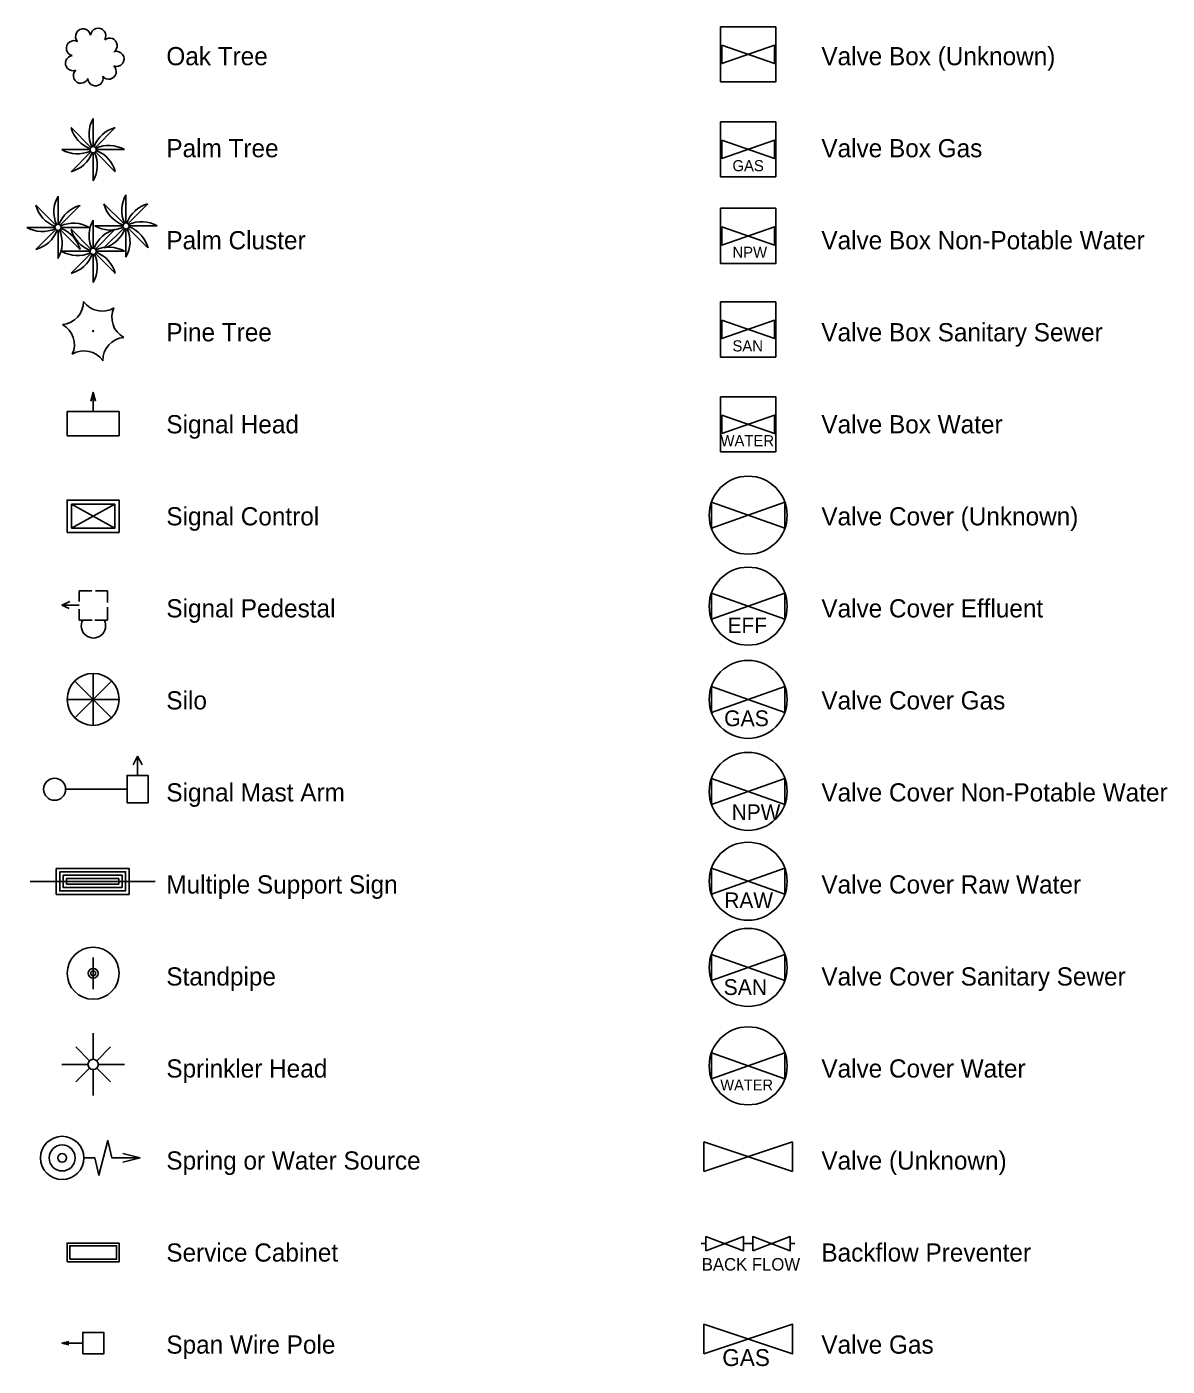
# Model space of a CAD drawing. Extents: x -371 to 730, y -9 to 425.
# Drawn here: x -72.1 to 37.6, y 165.4 to 294.2 of the extents above; entities that cross this region are included whole.
import ezdxf

# ---------------------------------------------------------------- set-up
doc = ezdxf.new("R2010")
doc.units = 0
for name, color, linetype in [('JunctBox_ep', 7, 'Continuous'), ('Signal_ep', 7, 'Continuous'), ('SignalSupport_ep', 7, 'Continuous'), ('SignMulti_ep', 7, 'Continuous'), ('Silo_ep', 7, 'Continuous'), ('SpanWire_ep', 7, 'Continuous'), ('Sprinkler_ep', 7, 'Continuous'), ('Tree_ep', 7, 'Continuous'), ('Tributary_ep', 7, 'Continuous'), ('Valve_ep', 7, 'Continuous'), ('ValveBFP_ep', 7, 'Continuous'), ('ValveCover_ep', 7, 'Continuous'), ('ValveCvrEff_ep', 7, 'Continuous'), ('ValveCvrGas_ep', 7, 'Continuous'), ('ValveCvrSewer_ep', 7, 'Continuous'), ('ValveCvrWater_ep', 7, 'Continuous'), ('ValveCvrWaterNP_ep', 7, 'Continuous'), ('ValveGas_ep', 7, 'Continuous'), ('ValveSewer_ep', 7, 'Continuous'), ('ValveWater_ep', 7, 'Continuous'), ('ValveWaterNP_ep', 7, 'Continuous'), ('WaterMisc_ep', 7, 'Continuous')]:
    doc.layers.add(name, color=color, linetype=linetype)

msp = doc.modelspace()

# ---------------------------------------------------------------- linework, layer by layer
for p, q in [((-65.71, 282.71), (-65.71, 285.41)), ((-65.92, 282.62), (-67.83, 284.53)), ((-65.5, 282.62), (-63.59, 284.53)), ((-66.01, 282.41), (-68.71, 282.41)), ((-65.92, 282.19), (-67.83, 280.28)), ((-65.71, 282.11), (-65.71, 279.41)), ((-65.5, 282.19), (-63.59, 280.28)), ((-65.41, 282.41), (-62.71, 282.41)), ((-69.3, 275.14), (-71.21, 277.05)), ((-69.09, 275.23), (-69.09, 277.93)), ((-68.88, 275.14), (-66.97, 277.05)), ((-62.77, 275.29), (-64.68, 277.2)), ((-62.56, 275.37), (-62.56, 278.07)), ((-62.35, 275.29), (-60.44, 277.2)), ((-69.39, 274.93), (-72.09, 274.93)), ((-69.3, 274.72), (-71.21, 272.81)), ((-69.09, 274.63), (-69.09, 271.93)), ((-68.88, 274.72), (-66.97, 272.81)), ((-68.79, 274.93), (-66.09, 274.93)), ((-65.92, 272.84), (-67.83, 274.75)), ((-65.71, 272.93), (-65.71, 275.63)), ((-62.86, 275.07), (-65.56, 275.07)), ((-65.5, 272.84), (-63.59, 274.75)), ((-62.77, 274.86), (-64.68, 272.95)), ((-62.56, 274.77), (-62.56, 272.07)), ((-62.35, 274.86), (-60.44, 272.95)), ((-62.26, 275.07), (-59.56, 275.07)), ((-66.01, 272.63), (-68.71, 272.63)), ((-65.92, 272.41), (-67.83, 270.51)), ((-65.71, 272.33), (-65.71, 269.63)), ((-65.5, 272.41), (-63.59, 270.51)), ((-65.41, 272.63), (-62.71, 272.63))]:
    msp.add_line(p, q)
for centre, radius, start, end in [((-63.11, 283.91), 3, 150, 204.268), ((-64.93, 285.3), 3, 195, 249.268), ((-62.81, 281.63), 3, 105, 159.268), ((-67.21, 285), 3, 240, 294.268), ((-68.61, 283.18), 3, 285, 339.268), ((-68.31, 280.91), 3, 330, 24.268), ((-64.21, 279.81), 3, 60, 114.268), ((-66.48, 279.51), 3, 15, 69.268), ((-68.32, 277.83), 3, 195, 249.268), ((-66.49, 276.43), 3, 150, 204.268), ((-66.19, 274.15), 3, 105, 159.268), ((-61.78, 277.97), 3, 195, 249.268), ((-59.96, 276.57), 3, 150, 204.268), ((-59.66, 274.3), 3, 105, 159.268), ((-70.59, 277.53), 3, 240, 294.268), ((-71.99, 275.71), 3, 285, 339.268), ((-71.69, 273.43), 3, 330, 24.268), ((-67.59, 272.33), 3, 60, 114.268), ((-69.87, 272.03), 3, 15, 69.268), ((-64.93, 275.52), 3, 195, 249.268), ((-63.11, 274.13), 3, 150, 204.268), ((-62.81, 271.85), 3, 105, 159.268), ((-64.06, 277.67), 3, 240, 294.268), ((-65.46, 275.85), 3, 285, 339.268), ((-65.16, 273.57), 3, 330, 24.268), ((-61.06, 272.48), 3, 60, 114.268), ((-63.33, 272.18), 3, 15, 69.268), ((-67.21, 275.22), 3, 240, 294.268), ((-68.61, 273.4), 3, 285, 339.268), ((-68.31, 271.13), 3, 330, 24.268), ((-64.21, 270.03), 3, 60, 114.268), ((-66.48, 269.73), 3, 15, 69.268), ((-68.84, 267.77), 2.2, 275.0912, 1.063), ((-64.84, 269.08), 2.2, 215.0912, 301.063), ((-61.71, 266.27), 2.2, 155.0912, 241.063), ((-69.71, 263.66), 2.2, 335.0912, 61.063), ((-62.58, 262.15), 2.2, 95.0912, 181.063), ((-66.58, 260.85), 2.2, 35.0912, 121.063)]:
    msp.add_arc(centre, radius, start, end)
at = {"layer": 'JunctBox_ep'}
for points in [[(-68.21, 175.45), (-63.21, 175.45), (-63.21, 177.25), (-68.21, 177.25)], [(-67.96, 175.7), (-63.46, 175.7), (-63.46, 177), (-67.96, 177)]]:
    msp.add_lwpolyline(points, close=True, dxfattribs=at)
at = {"layer": 'Signal_ep'}
for p, q in [((-65.71, 259.06), (-65.71, 257.22)), ((-68.21, 254.87), (-68.21, 257.22)), ((-68.21, 257.22), (-65.71, 257.22)), ((-65.71, 257.22), (-63.21, 257.22)), ((-63.21, 257.22), (-63.21, 254.87)), ((-63.21, 254.87), (-68.21, 254.87)), ((-67.05, 239.97), (-65.84, 239.97)), ((-67.05, 239.97), (-67.05, 238.95)), ((-64.32, 239.97), (-65.49, 239.97)), ((-64.32, 239.97), (-64.32, 238.86)), ((-68.71, 238.59), (-67.96, 238.94)), ((-67.07, 238.59), (-68.71, 238.59)), ((-68.71, 238.59), (-68.03, 238.28)), ((-64.32, 237.17), (-64.32, 238.41)), ((-67.05, 237.17), (-67.05, 238.22)), ((-67.05, 237.17), (-65.81, 237.17)), ((-64.32, 237.17), (-65.54, 237.17))]:
    msp.add_line(p, q, dxfattribs=at)
msp.add_lwpolyline([(-65.92, 258.22), (-65.71, 259.06), (-65.5, 258.22)], dxfattribs=at)
msp.add_arc((-65.68, 236.61), 1.17, 151.4252, 28.5748, dxfattribs=at)
at = {"layer": 'SignalSupport_ep'}
for p, q in [((-67.79, 248.3), (-63.62, 246.01)), ((-63.62, 248.3), (-67.79, 246.01)), ((-61.85, 223.23), (-61.43, 224.07)), ((-61.43, 224.08), (-61.43, 222.22)), ((-61.43, 224.07), (-61, 223.23)), ((-68.36, 220.9), (-62.44, 220.9))]:
    msp.add_line(p, q, dxfattribs=at)
for points in [[(-68.21, 245.59), (-63.21, 245.59), (-63.21, 248.71), (-68.21, 248.71)], [(-67.79, 246.01), (-63.62, 246.01), (-63.62, 248.3), (-67.79, 248.3)], [(-62.44, 219.59), (-60.42, 219.59), (-60.42, 222.22), (-62.44, 222.22)]]:
    msp.add_lwpolyline(points, close=True, dxfattribs=at)
msp.add_circle((-69.42, 220.9), 1.06, dxfattribs=at)
at = {"layer": 'SignMulti_ep'}
msp.add_line((-71.76, 212.04), (-59.76, 212.04), dxfattribs=at)
for points in [[(-69.26, 213.29), (-62.26, 213.29), (-62.26, 210.79), (-69.26, 210.79)], [(-68.93, 212.96), (-62.59, 212.96), (-62.59, 211.12), (-68.93, 211.12)], [(-68.6, 212.63), (-62.92, 212.63), (-62.92, 211.45), (-68.6, 211.45)], [(-68.27, 212.3), (-63.25, 212.3), (-63.25, 211.78), (-68.27, 211.78)]]:
    msp.add_lwpolyline(points, close=True, dxfattribs=at)
at = {"layer": 'Silo_ep'}
for q in [(-65.71, 232.04), (-67.48, 231.3), (-63.94, 231.3), (-68.21, 229.54), (-67.48, 227.77), (-65.71, 227.04), (-63.94, 227.77), (-63.21, 229.54)]:
    msp.add_line((-65.71, 229.54), q, dxfattribs=at)
msp.add_circle((-65.71, 229.54), 2.5, dxfattribs=at)
at = {"layer": 'SpanWire_ep'}
msp.add_line((-66.71, 167.63), (-68.71, 167.63), dxfattribs=at)
msp.add_lwpolyline([(-68.04, 167.46), (-68.71, 167.63), (-68.04, 167.8)], dxfattribs=at)
msp.add_lwpolyline([(-66.71, 166.6), (-64.69, 166.6), (-64.69, 168.66), (-66.71, 168.66)], close=True, dxfattribs=at)
at = {"layer": 'Sprinkler_ep'}
for p, q in [((-65.71, 197.43), (-65.71, 194.93)), ((-67.39, 196.11), (-66.06, 194.79)), ((-65.35, 194.79), (-64.03, 196.11)), ((-66.21, 194.43), (-68.71, 194.43)), ((-67.39, 192.75), (-66.06, 194.08)), ((-65.71, 193.93), (-65.71, 191.43)), ((-65.35, 194.08), (-64.03, 192.75)), ((-62.71, 194.43), (-65.21, 194.43))]:
    msp.add_line(p, q, dxfattribs=at)
msp.add_circle((-65.71, 194.43), 0.5, dxfattribs=at)
at = {"layer": 'Tree_ep'}
for centre, radius in [((-65.71, 282.41), 0.3), ((-69.09, 274.93), 0.3), ((-62.56, 275.07), 0.3), ((-65.71, 272.63), 0.3), ((-65.71, 264.96), 0.05)]:
    msp.add_circle(centre, radius, dxfattribs=at)
for centre, start, end in [((-66.67, 293.29), 8.8323, 223.0894), ((-65.22, 293.35), 329.0529, 175.9516), ((-67.56, 292.16), 60.6582, 257.701), ((-64.13, 292.41), 305.7255, 129.4527), ((-67.65, 290.72), 95.0054, 290.1691), ((-63.47, 291.13), 249.5509, 108.9453), ((-66.89, 289.51), 133.5142, 339.6763), ((-64.21, 289.91), 217.612, 48.6604), ((-65.48, 289.26), 180.0519, 16.2112)]:
    msp.add_arc(centre, 0.728, start, end, dxfattribs=at)
at = {"layer": 'Tributary_ep'}
for points in [[(-66.6, 185.44), (-65.56, 185.44), (-65.15, 183.77), (-64.31, 187.11), (-63.9, 185.44), (-61.19, 185.44)], [(-62.85, 185.02), (-61.19, 185.44), (-62.85, 185.86)]]:
    msp.add_lwpolyline(points, dxfattribs=at)
for radius in [2.08, 1.25, 0.417]:
    msp.add_circle((-68.69, 185.44), radius, dxfattribs=at)
at = {"layer": 'Valve_ep'}
for p, q in [((-6.99, 184.14), (-6.99, 186.99)), ((-6.99, 186.99), (1.55, 184.14)), ((1.55, 186.99), (-6.99, 184.14)), ((1.55, 184.14), (1.55, 186.99))]:
    msp.add_line(p, q, dxfattribs=at)
for points in [[(-5.37, 294.22), (-0.07, 294.22), (-0.07, 288.92), (-5.37, 288.92)], [(-5.26, 292.45), (-0.18, 290.68), (-0.18, 292.45), (-5.26, 290.68)]]:
    msp.add_lwpolyline(points, close=True, dxfattribs=at)
at = {"layer": 'ValveBFP_ep'}
for points in [[(-6.78, 176.52), (-6.78, 177.87), (-3.18, 176.52), (-3.18, 177.87)], [(-2.28, 176.52), (-2.28, 177.87), (1.32, 176.52), (1.32, 177.87)]]:
    msp.add_lwpolyline(points, close=True, dxfattribs=at)
for points in [[(-7.23, 177.2), (-6.78, 177.2)], [(-3.18, 177.2), (-2.28, 177.2)], [(1.32, 177.2), (1.77, 177.2)]]:
    msp.add_lwpolyline(points, dxfattribs=at)
at = {"layer": 'ValveCover_ep'}
for p, q in [((-6.25, 248.5), (0.82, 246)), ((0.82, 248.5), (-6.25, 246)), ((-6.25, 246), (-6.25, 248.5)), ((0.82, 246), (0.82, 248.5))]:
    msp.add_line(p, q, dxfattribs=at)
msp.add_circle((-2.72, 247.25), 3.75, dxfattribs=at)
at = {"layer": 'ValveCvrEff_ep'}
msp.add_lwpolyline([(-6.25, 237.25), (-6.25, 239.75), (0.82, 237.25), (0.82, 239.75)], close=True, dxfattribs=at)
msp.add_circle((-2.72, 238.5), 3.75, dxfattribs=at)
at = {"layer": 'ValveCvrGas_ep'}
msp.add_lwpolyline([(-6.25, 230.79), (0.82, 228.29), (0.82, 230.79), (-6.25, 228.29)], close=True, dxfattribs=at)
msp.add_circle((-2.72, 229.54), 3.75, dxfattribs=at)
at = {"layer": 'ValveCvrSewer_ep'}
for p, q in [((-6.25, 205.01), (0.82, 202.51)), ((0.82, 205.01), (-6.25, 202.51)), ((-6.25, 202.51), (-6.25, 205.01)), ((0.82, 202.51), (0.82, 205.01))]:
    msp.add_line(p, q, dxfattribs=at)
msp.add_circle((-2.72, 203.76), 3.75, dxfattribs=at)
at = {"layer": 'ValveCvrWater_ep'}
for p, q in [((-6.25, 195.55), (0.82, 193.05)), ((0.82, 195.55), (-6.25, 193.05)), ((-6.25, 193.05), (-6.25, 195.55)), ((0.82, 193.05), (0.82, 195.55))]:
    msp.add_line(p, q, dxfattribs=at)
msp.add_circle((-2.72, 194.3), 3.75, dxfattribs=at)
at = {"layer": 'ValveCvrWaterNP_ep'}
for points in [[(-6.25, 221.94), (0.82, 219.44), (0.82, 221.94), (-6.25, 219.44)], [(-6.25, 210.8), (-6.25, 213.3), (0.82, 210.8), (0.82, 213.3)]]:
    msp.add_lwpolyline(points, close=True, dxfattribs=at)
for centre in [(-2.72, 220.69), (-2.72, 212.05)]:
    msp.add_circle(centre, 3.75, dxfattribs=at)
at = {"layer": 'ValveGas_ep'}
for points in [[(-5.37, 285.09), (-0.07, 285.09), (-0.07, 279.79), (-5.37, 279.79)], [(-5.26, 283.32), (-0.18, 281.56), (-0.18, 283.32), (-5.26, 281.56)], [(-6.99, 166.61), (-6.99, 169.45), (1.55, 166.61), (1.55, 169.45)]]:
    msp.add_lwpolyline(points, close=True, dxfattribs=at)
at = {"layer": 'ValveSewer_ep'}
for points in [[(-5.37, 267.76), (-0.07, 267.76), (-0.07, 262.46), (-5.37, 262.46)], [(-5.26, 266), (-0.18, 264.23), (-0.18, 266), (-5.26, 264.23)]]:
    msp.add_lwpolyline(points, close=True, dxfattribs=at)
at = {"layer": 'ValveWater_ep'}
for points in [[(-5.37, 258.64), (-0.07, 258.64), (-0.07, 253.33), (-5.37, 253.33)], [(-5.26, 256.87), (-0.18, 255.1), (-0.18, 256.87), (-5.26, 255.1)]]:
    msp.add_lwpolyline(points, close=True, dxfattribs=at)
at = {"layer": 'ValveWaterNP_ep'}
for points in [[(-5.37, 276.76), (-0.07, 276.76), (-0.07, 271.45), (-5.37, 271.45)], [(-5.26, 274.99), (-0.18, 273.22), (-0.18, 274.99), (-5.26, 273.22)]]:
    msp.add_lwpolyline(points, close=True, dxfattribs=at)
at = {"layer": 'WaterMisc_ep'}
msp.add_line((-65.71, 201.68), (-65.71, 204.71), dxfattribs=at)
for radius in [2.5, 0.474, 0.239]:
    msp.add_circle((-65.71, 203.2), radius, dxfattribs=at)

# ---------------------------------------------------------------- texts
for s, p in [('Oak Tree', (-58.67, 290.52)), ('Valve Box (Unknown)', (4.32, 290.52)), ('Palm Tree', (-58.67, 281.67)), ('Valve Box Gas', (4.32, 281.67)), ('Palm Cluster', (-58.67, 272.82)), ('Valve Box Non-Potable Water', (4.32, 272.82)), ('Pine Tree', (-58.67, 263.97)), ('Valve Box Sanitary Sewer', (4.32, 263.97)), ('Signal Head', (-58.67, 255.12)), ('Valve Box Water', (4.32, 255.12)), ('Signal Control', (-58.67, 246.27)), ('Valve Cover (Unknown)', (4.32, 246.27)), ('Signal Pedestal', (-58.67, 237.42)), ('Valve Cover Effluent', (4.32, 237.42)), ('Silo', (-58.67, 228.57)), ('Valve Cover Gas', (4.32, 228.57)), ('Signal Mast Arm', (-58.67, 219.72)), ('Valve Cover Non-Potable Water', (4.32, 219.72)), ('Multiple Support Sign', (-58.67, 210.87)), ('Valve Cover Raw Water', (4.32, 210.87)), ('Standpipe', (-58.67, 202.02)), ('Valve Cover Sanitary Sewer', (4.32, 202.02)), ('Sprinkler Head', (-58.67, 193.17)), ('Valve Cover Water', (4.32, 193.17)), ('Spring or Water Source', (-58.67, 184.32)), ('Valve (Unknown)', (4.32, 184.32)), ('Service Cabinet', (-58.67, 175.47)), ('Backflow Preventer', (4.32, 175.47)), ('Span Wire Pole', (-58.67, 166.62)), ('Valve Gas', (4.32, 166.62))]:
    msp.add_text(s, height=1.75).set_placement(p)
at = {"layer": 'ValveBFP_ep'}
msp.add_text('BACK FLOW', height=1.2, dxfattribs=at).set_placement((-7.18, 174.61))
at = {"layer": 'ValveCvrEff_ep'}
msp.add_text('EFF', height=1.5, dxfattribs=at).set_placement((-4.7, 235.91))
at = {"layer": 'ValveCvrGas_ep'}
msp.add_text('GAS', height=1.522, dxfattribs=at).set_placement((-5.03, 226.96))
at = {"layer": 'ValveCvrSewer_ep'}
msp.add_text('SAN', height=1.522, dxfattribs=at).set_placement((-5.08, 201.11))
at = {"layer": 'ValveCvrWater_ep'}
msp.add_text('WATER', height=1.05, dxfattribs=at).set_placement((-5.4, 191.93))
at = {"layer": 'ValveCvrWaterNP_ep'}
for s, p in [('NPW', (-4.3, 217.94)), ('RAW', (-5.01, 209.47))]:
    msp.add_text(s, height=1.5, dxfattribs=at).set_placement(p)
at = {"layer": 'ValveGas_ep'}
for height, p in [(1.067, (-4.23, 280.33)), (1.622, (-5.21, 165.43))]:
    msp.add_text('GAS', height=height, dxfattribs=at).set_placement(p)
at = {"layer": 'ValveSewer_ep'}
msp.add_text('SAN', height=1.067, dxfattribs=at).set_placement((-4.23, 263))
at = {"layer": 'ValveWater_ep'}
msp.add_text('WATER', height=1.067, dxfattribs=at).set_placement((-5.38, 253.88))
at = {"layer": 'ValveWaterNP_ep'}
msp.add_text('NPW', height=1.067, dxfattribs=at).set_placement((-4.23, 272))

doc.saveas('drawing.dxf')
